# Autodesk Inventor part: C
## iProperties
Created: 2007-08
Part Number: C
Document SubType Name: Modeling
Designer: t-ikumi
Author: t-ikumi
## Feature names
1. 押し出し1 [Extrusion]
2. 押し出し2 [Extrusion]
3. 押し出し3 [Extrusion]
4. 面取り1 [Chamfer]
5. 押し出し4 [Extrusion]
6. フィレット1 [Fillet]
